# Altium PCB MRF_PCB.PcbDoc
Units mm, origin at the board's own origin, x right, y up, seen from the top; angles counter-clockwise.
Board outline 35 x 20 mm, 2 copper layers (Top Layer, Bottom Layer); 9 components, 16 nets, 39 pads, 10 vias.
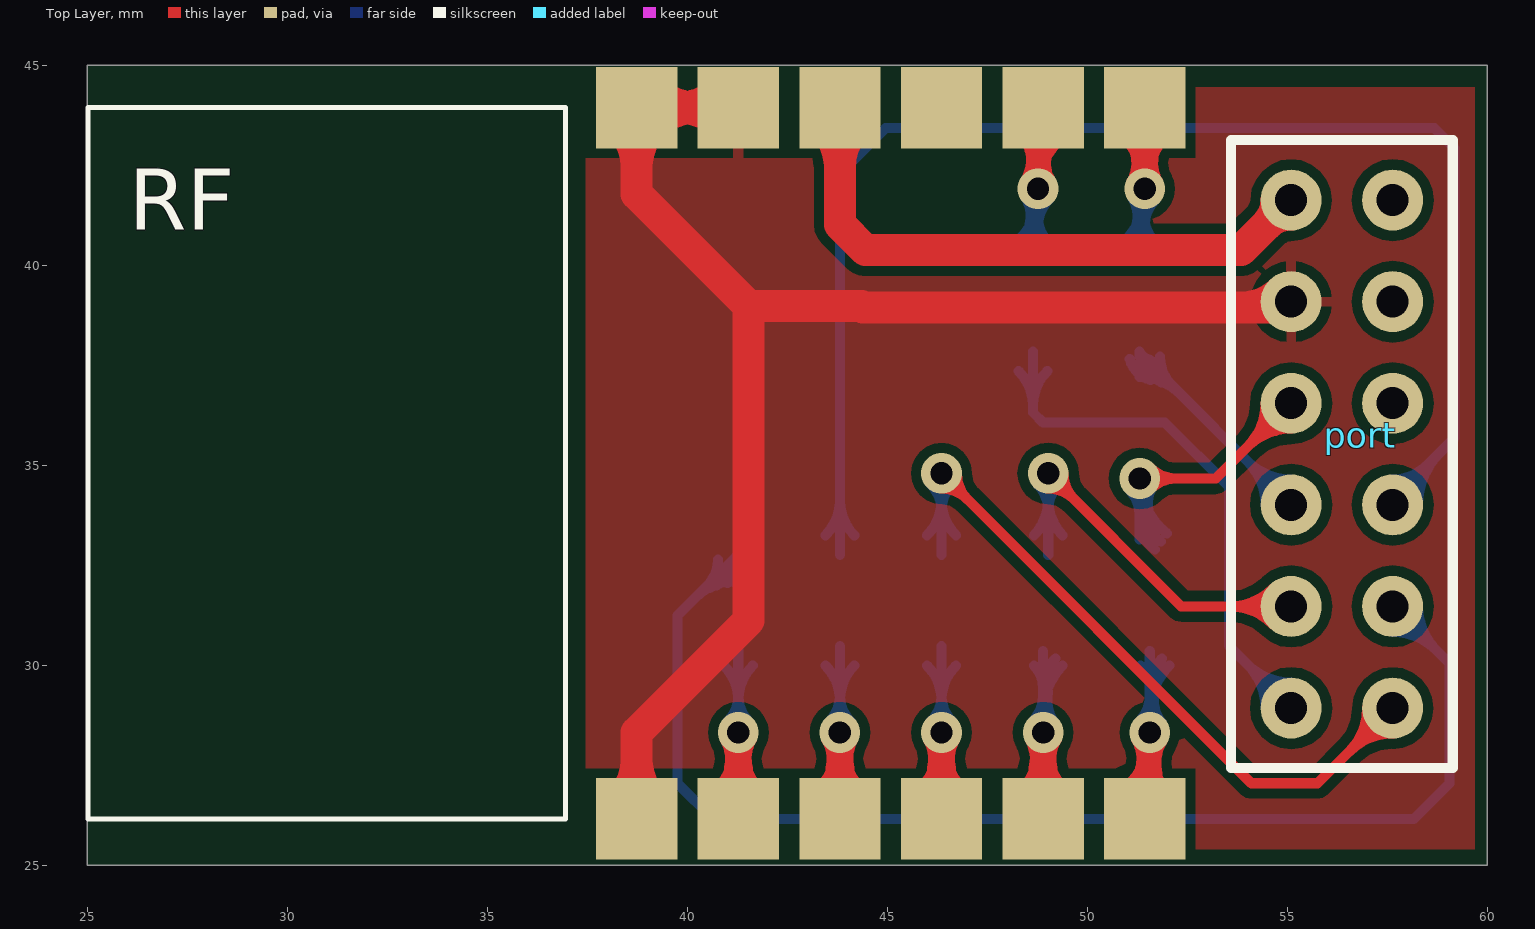
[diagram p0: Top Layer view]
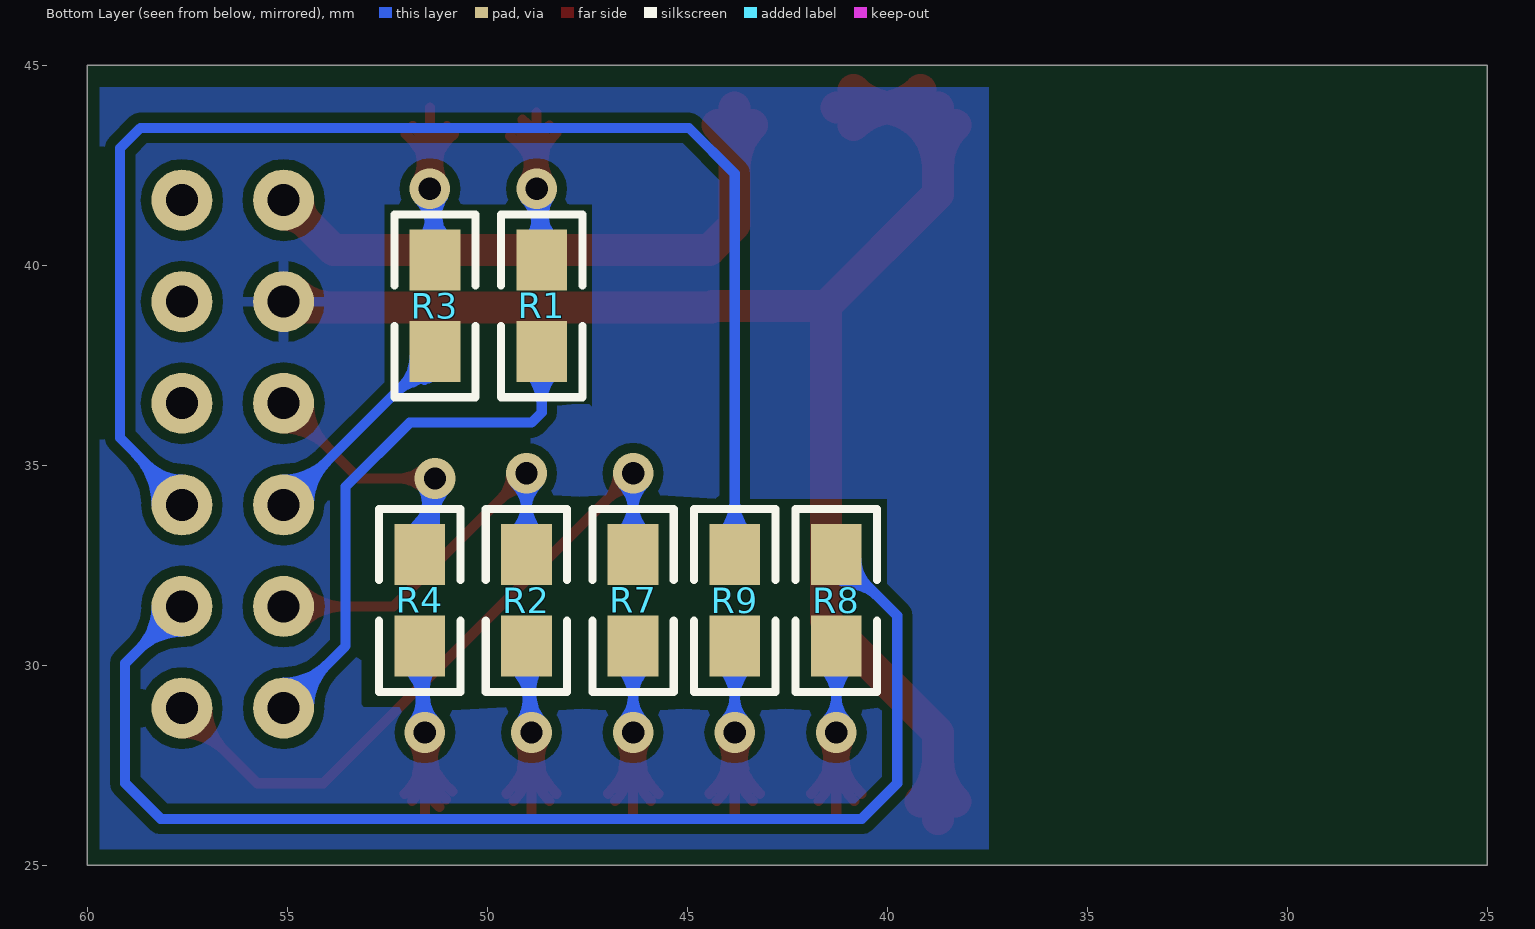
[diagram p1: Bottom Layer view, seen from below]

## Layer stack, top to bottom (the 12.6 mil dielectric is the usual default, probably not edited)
Top Solder: solder mask 0.0102, Solder Resist, Dk 3.5
Top Layer: signal copper 0.0356
Dielectric 1: dielectric 0.32, FR-4, Dk 4.8
Bottom Layer: signal copper 0.0356
Bottom Solder: solder mask 0.0102, Solder Resist, Dk 3.5

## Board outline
25,25 60,25 60,45 25,45

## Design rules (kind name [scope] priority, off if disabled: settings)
Clearance [All] p1: gap=0.254
PolygonConnect [All] p1: connectstyle=Relief reliefconductorwidth=0.254 reliefentries=4 polygonreliefangle="90 Angle" airgapwidth=0.254
RoutingVias [All] p1: holewidth=0.711 width=1.27 viastyle="Through Hole" minholewidth=0.711 minwidth=1.27 maxholewidth=0.711 maxwidth=1.27
SolderMaskExpansion [All] p1: expansion=0.102
Width [All] p1: maxlimit=0.8 minlimit=0.254 preferedwidth=0.254
29 further rules are at their usual default settings.

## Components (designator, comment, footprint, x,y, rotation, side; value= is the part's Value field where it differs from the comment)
port "Port" Port 53.594,27.432 r0 top
R1 "Res2" 0805 48.641,40.132 r270 bottom
R2 "Res2" 0805 49.022,30.48 r90 bottom
R3 "Res2" 0805 51.308,40.132 r270 bottom
R4 "Res2" 0805 51.689,30.48 r90 bottom
R7 "Res2" 0805 46.355,30.48 r90 bottom
R8 "Res2" 0805 41.275,30.48 r90 bottom
R9 "Res2" 0805 43.815,30.48 r90 bottom
RF "MRF Chip" MRF 25.019,26.162 r0 top

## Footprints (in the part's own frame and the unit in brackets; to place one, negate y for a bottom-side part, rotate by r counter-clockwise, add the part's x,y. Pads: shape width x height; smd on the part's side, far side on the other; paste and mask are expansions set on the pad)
0805 [mil]
  rect 60x50 smd: 1(0,0) 2(90,0)
  silkscreen extent -45,-40 135,40
MRF [mil]
  rect 80x80 smd: 1(540,0) 2(640,0) 3(740,0) 4(840,0) 5(940,0) 6(1040,0) 7(1040,700) 8(940,700) 9(840,700) 10(740,700) 11(640,700) 12(540,700)
  silkscreen extent 0,0 470,700
Port [mil] "Port 2x6"
  round 60 hole 31.5: 1(59.06,59.06) 2(59.06,159.06) 3(59.06,259.06) 4(59.06,359.06) 5(59.06,459.06) 6(59.06,559.06) 7(159.06,59.06) 8(159.06,159.06) 9(159.06,259.06) 10(159.06,359.06) 11(159.06,459.06) 12(159.06,559.06)
  round 19.68 on Top Overlay: 2(195,595)
  silkscreen extent 0,0 218,618

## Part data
R1 R2 R3 R4 R7 R8 R9: "Resistor"

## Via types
v1: diameter 1.016, hole 0.559, Top Layer to Bottom Layer, 10 vias

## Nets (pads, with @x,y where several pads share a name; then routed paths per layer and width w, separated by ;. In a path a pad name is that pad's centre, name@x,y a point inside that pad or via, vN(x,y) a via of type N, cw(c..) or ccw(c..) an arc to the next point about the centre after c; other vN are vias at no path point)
N1: R1.1 RF.8 | length 41.7
  Top Layer w0.254: v1(48.768,41.91) RF.8@48.768,43.815 ; v1@48.446,42.113 ccw(c47.631,42.626) 48.561,42.875 ; v1@48.446,42.113 ccw(c47.631,42.626) 48.561,42.875 ; v1@48.446,42.113 ccw(c47.631,42.626) 48.561,42.875 ; v1@48.578,42.24 ccw(c48.341,42.65) 48.798,42.527 ; v1@48.578,42.24 ccw(c48.341,42.65) 48.798,42.527 ; v1@48.578,42.24 ccw(c48.341,42.65) 48.798,42.527 ; v1@48.595,42.25 ccw(c48.247,42.937) 48.991,42.737 ; v1@48.595,42.25 ccw(c48.247,42.937) 48.991,42.737 ; v1@48.595,42.25 ccw(c48.247,42.937) 48.991,42.737 ; 48.609,42.695 ccw(c49.333,42.889) v1@48.959,42.24 ; 48.609,42.695 ccw(c49.333,42.889) v1@48.959,42.24 ; 48.609,42.695 ccw(c49.333,42.889) v1@48.959,42.24 ; 48.768,42.83 cw(c47.848,42.83) 48.499,42.179 ccw(c47.848,42.83) 48.768,42.83 ; 48.768,42.83 ccw(c49.688,42.83) 49.037,42.179 cw(c49.688,42.83) 48.768,42.83 ; 48.88,42.834 ccw(c49.561,42.652) v1@49.046,42.17 ; 48.88,42.834 ccw(c49.561,42.652) v1@49.046,42.17 ; 48.88,42.834 ccw(c49.561,42.652) v1@49.046,42.17 ; 48.991,42.737 ccw(c49.739,42.537) v1@49.088,42.117 ; 48.991,42.737 ccw(c49.739,42.537) v1@49.088,42.117 ; 48.991,42.737 ccw(c49.739,42.537) v1@49.088,42.117 ; RF.8@48.266,43.313 cw(c47.055,42.102) 48.768,42.102 ccw(c47.055,42.102) RF.8@48.266,43.313 ; RF.8@48.446,43.493 cw(c47.669,42.716) 48.768,42.716 ccw(c47.669,42.716) RF.8@48.446,43.493 ; v1@48.768,41.906 cw(c50.427,41.906) 49.429,43.232 ccw(c50.427,41.906) v1@48.768,41.906 ; v1@48.768,42.415 cw(c50.044,42.415) 49.277,43.435 ccw(c50.044,42.415) v1@48.768,42.415 ; 48.768,42.924 cw(c49.661,42.924) 49.124,43.638 ccw(c49.661,42.924) 48.768,42.924
  Bottom Layer w0.254: R1.1@48.768,40.259 v1(48.768,41.91) ; v1@48.449,41.701 cw(c47.735,41.234) 48.559,41.013 ; v1@48.449,41.701 cw(c47.735,41.234) 48.559,41.013 ; v1@48.449,41.701 cw(c47.735,41.234) 48.559,41.013 ; 48.579,41.085 cw(c49.366,40.874) v1@48.959,41.58 ; 48.579,41.085 cw(c49.366,40.874) v1@48.959,41.58 ; 48.579,41.085 cw(c49.366,40.874) v1@48.959,41.58 ; 48.768,40.99 cw(c49.688,40.99) 49.037,41.641 ccw(c49.688,40.99) 48.768,40.99 ; 48.768,40.99 ccw(c47.848,40.99) 48.499,41.641 cw(c47.848,40.99) 48.768,40.99 ; 48.768,41.179 cw(c47.721,41.179) 48.461,40.439 ccw(c47.721,41.179) 48.768,41.179 ; 48.768,41.179 ccw(c49.561,41.179) 49,40.618 cw(c49.561,41.179) 48.768,41.179 ; R1.1@48.282,40.618 ccw(c47.108,41.792) 48.768,41.792 cw(c47.108,41.792) R1.1@48.282,40.618
N2: R2.1 RF.5 | length 26.1
  Top Layer w0.254: RF.5@48.266,26.791 ccw(c46.749,28.308) 48.895,28.308 ccw(c51.041,28.308) RF.5@49.524,26.791 ; RF.5@48.446,26.611 ccw(c47.362,27.695) 48.895,27.695 ccw(c50.428,27.695) RF.5@49.344,26.611 ; v1@48.565,28.131 cw(c47.759,27.665) 48.658,27.424 ; v1@48.626,28.052 cw(c47.975,27.401) 48.895,27.401 cw(c49.815,27.401) v1@49.164,28.052 ; 48.662,27.439 cw(c49.54,27.204) v1@49.085,27.991 ; v1@48.705,27.991 cw(c48.25,27.204) 49.128,27.439 ; RF.5 v1(48.895,28.321) ; 49.132,27.424 cw(c50.031,27.665) v1@49.225,28.131
  Bottom Layer w0.254: v1(48.895,28.321) R2.1@48.895,30.353 ; 48.895,29.241 cw(c47.975,29.241) 48.626,28.59 ccw(c47.975,29.241) 48.895,29.241 ; 48.895,29.241 ccw(c49.815,29.241) 49.164,28.59 cw(c49.815,29.241) 48.895,29.241 ; 48.895,29.433 cw(c49.942,29.433) 49.202,30.173 ccw(c49.942,29.433) 48.895,29.433 ; 48.895,29.433 ccw(c48.102,29.433) 48.663,29.994 cw(c48.102,29.433) 48.895,29.433 ; v1@48.696,28.646 ccw(c48.421,29.092) 48.931,28.97 cw(c48.421,29.092) v1@48.696,28.646 ; v1@48.895,28.82 cw(c50.555,28.82) 49.381,29.994 ccw(c50.555,28.82) v1@48.895,28.82 ; 48.899,28.836 ccw(c49.399,28.717) 48.995,28.4 cw(c49.399,28.717) 48.899,28.836 ; 49.021,29.347 ccw(c49.925,29.131) 49.194,28.557 cw(c49.925,29.131) 49.021,29.347
N3: R3.1 RF.7 | length 25.8
  Top Layer w0.254: RF.7@50.832,43.289 cw(c49.557,41.91) v1(51.435,41.91) ; RF.7@51.004,43.476 cw(c50.094,42.491) 51.435,42.491 cw(c52.776,42.491) RF.7@51.866,43.476 ; v1@51.105,42.1 ccw(c50.308,42.56) 51.197,42.799 ccw(c52.085,43.036) v1@51.625,42.24 ; v1@51.166,42.179 ccw(c50.515,42.83) 51.435,42.83 ccw(c52.355,42.83) v1@51.704,42.179 ; v1@51.245,42.24 ccw(c50.785,43.036) 51.673,42.798 ccw(c52.562,42.56) v1@51.765,42.1 ; RF.7 v1(51.435,41.91) ; RF.7@52.038,43.289 ccw(c53.313,41.91) v1(51.435,41.91)
  Bottom Layer w0.254: R3.1@51.435,40.259 v1(51.435,41.91) ; v1@51.116,41.701 cw(c50.402,41.234) 51.226,41.013 ; v1@51.116,41.701 cw(c50.402,41.234) 51.226,41.013 ; v1@51.116,41.701 cw(c50.402,41.234) 51.226,41.013 ; 51.246,41.085 cw(c52.033,40.874) v1@51.626,41.58 ; 51.246,41.085 cw(c52.033,40.874) v1@51.626,41.58 ; 51.246,41.085 cw(c52.033,40.874) v1@51.626,41.58 ; 51.435,40.99 cw(c52.355,40.99) 51.704,41.641 ccw(c52.355,40.99) 51.435,40.99 ; 51.435,40.99 ccw(c50.515,40.99) 51.166,41.641 cw(c50.515,40.99) 51.435,40.99 ; 51.435,41.179 cw(c50.388,41.179) 51.128,40.439 ccw(c50.388,41.179) 51.435,41.179 ; 51.435,41.179 ccw(c52.228,41.179) 51.667,40.618 cw(c52.228,41.179) 51.435,41.179 ; R3.1@50.949,40.618 ccw(c49.775,41.792) 51.435,41.792 cw(c49.775,41.792) R3.1@50.949,40.618
N4: R4.1 RF.6 | length 26.2
  Top Layer w0.254: RF.6@50.868,26.847 ccw(c49.649,28.321) v1(51.562,28.321) RF.6@51.562,26.289 ; RF.6@51.03,26.651 ccw(c50.096,27.781) 51.562,27.781 ; RF.6@51.192,26.456 ccw(c50.542,27.241) 51.562,27.241 ; v1@51.232,28.13 cw(c50.435,27.671) 51.324,27.432 cw(c52.212,27.195) v1@51.753,27.991 ; v1@51.293,28.052 cw(c50.642,27.401) 51.562,27.401 cw(c52.482,27.401) v1@51.831,28.052 ; v1@51.372,27.991 cw(c51.053,27.439) 51.669,27.604 ; 51.562,27.388 ccw(c52.661,27.388) RF.6@51.884,26.611 ; v1@51.562,28.002 ccw(c53.275,28.002) RF.6@52.064,26.791 ; 51.754,27.284 cw(c52.763,27.554) v1@51.883,28.116
  Bottom Layer w0.254: v1(51.562,28.321) R4.1@51.562,30.353 ; 51.562,29.241 cw(c50.642,29.241) 51.293,28.59 ccw(c50.642,29.241) 51.562,29.241 ; 51.562,29.241 ccw(c52.482,29.241) 51.831,28.59 cw(c52.482,29.241) 51.562,29.241 ; 51.562,29.433 cw(c52.609,29.433) 51.869,30.173 ccw(c52.609,29.433) 51.562,29.433 ; 51.562,29.433 ccw(c50.769,29.433) 51.33,29.994 cw(c50.769,29.433) 51.562,29.433 ; v1@51.363,28.646 ccw(c51.088,29.092) 51.598,28.97 cw(c51.088,29.092) v1@51.363,28.646 ; v1@51.562,28.82 cw(c53.222,28.82) 52.048,29.994 ccw(c53.222,28.82) v1@51.562,28.82 ; 51.566,28.836 ccw(c52.066,28.717) 51.662,28.4 cw(c52.066,28.717) 51.566,28.836 ; 51.688,29.347 ccw(c52.592,29.131) 51.861,28.557 cw(c52.592,29.131) 51.688,29.347
N7: R7.1 RF.4 | length 21.2
  Top Layer w0.254: RF.4@45.726,26.791 ccw(c44.209,28.308) 46.355,28.308 ccw(c48.501,28.308) RF.4@46.984,26.791 ; RF.4@45.906,26.611 ccw(c44.822,27.695) 46.355,27.695 ccw(c47.888,27.695) RF.4@46.804,26.611 ; v1@46.025,28.131 cw(c45.219,27.665) 46.118,27.424 ; v1@46.086,28.052 cw(c45.435,27.401) 46.355,27.401 cw(c47.275,27.401) v1@46.624,28.052 ; 46.122,27.439 cw(c47,27.204) v1@46.545,27.991 ; v1@46.165,27.991 cw(c45.71,27.204) 46.588,27.439 ; RF.4 v1(46.355,28.321) ; 46.592,27.424 cw(c47.491,27.665) v1@46.685,28.131
  Bottom Layer w0.254: v1(46.355,28.321) R7.1 ; 46.355,29.127 cw(c47.581,29.127) 46.714,29.994 ccw(c47.581,29.127) 46.355,29.127 ; 46.355,29.127 ccw(c45.129,29.127) 45.996,29.994 cw(c45.129,29.127) 46.355,29.127 ; 46.355,29.241 cw(c45.435,29.241) 46.086,28.59 ccw(c45.435,29.241) 46.355,29.241 ; 46.355,29.241 ccw(c47.275,29.241) 46.624,28.59 cw(c47.275,29.241) 46.355,29.241
N8: R8.1 RF.2 | length 21.2
  Top Layer w0.254: RF.2@40.646,26.791 ccw(c39.129,28.308) 41.275,28.308 ccw(c43.421,28.308) RF.2@41.904,26.791 ; RF.2@40.826,26.611 ccw(c39.742,27.695) 41.275,27.695 ccw(c42.808,27.695) RF.2@41.724,26.611 ; v1@40.945,28.131 cw(c40.139,27.665) 41.038,27.424 ; v1@41.006,28.052 cw(c40.355,27.401) 41.275,27.401 cw(c42.195,27.401) v1@41.544,28.052 ; 41.042,27.439 cw(c41.92,27.204) v1@41.465,27.991 ; v1@41.085,27.991 cw(c40.63,27.204) 41.508,27.439 ; RF.2 v1(41.275,28.321) ; 41.512,27.424 cw(c42.411,27.665) v1@41.605,28.131
  Bottom Layer w0.254: v1(41.275,28.321) R8.1 ; 41.275,29.127 cw(c42.501,29.127) 41.634,29.994 ccw(c42.501,29.127) 41.275,29.127 ; 41.275,29.127 ccw(c40.049,29.127) 40.916,29.994 cw(c40.049,29.127) 41.275,29.127 ; 41.275,29.241 cw(c40.355,29.241) 41.006,28.59 ccw(c40.355,29.241) 41.275,29.241 ; 41.275,29.241 ccw(c42.195,29.241) 41.544,28.59 cw(c42.195,29.241) 41.275,29.241
N9: R9.1 RF.3 | length 21.2
  Top Layer w0.254: RF.3@43.186,26.791 ccw(c41.669,28.308) 43.815,28.308 ccw(c45.961,28.308) RF.3@44.444,26.791 ; RF.3@43.366,26.611 ccw(c42.282,27.695) 43.815,27.695 ccw(c45.348,27.695) RF.3@44.264,26.611 ; v1@43.485,28.131 cw(c42.679,27.665) 43.578,27.424 ; v1@43.546,28.052 cw(c42.895,27.401) 43.815,27.401 cw(c44.735,27.401) v1@44.084,28.052 ; 43.582,27.439 cw(c44.46,27.204) v1@44.005,27.991 ; v1@43.625,27.991 cw(c43.17,27.204) 44.048,27.439 ; RF.3 v1(43.815,28.321) ; 44.052,27.424 cw(c44.951,27.665) v1@44.145,28.131
  Bottom Layer w0.254: v1(43.815,28.321) R9.1 ; 43.815,29.127 cw(c45.041,29.127) 44.174,29.994 ccw(c45.041,29.127) 43.815,29.127 ; 43.815,29.127 ccw(c42.589,29.127) 43.456,29.994 cw(c42.589,29.127) 43.815,29.127 ; 43.815,29.241 cw(c42.895,29.241) 43.546,28.59 ccw(c42.895,29.241) 43.815,29.241 ; 43.815,29.241 ccw(c44.735,29.241) 44.084,28.59 cw(c44.735,29.241) 43.815,29.241
P1: port.1 R1.2 | length 21.1
  Bottom Layer w0.254: R1.2 48.641,36.322 48.895,36.068 51.943,36.068 53.546,34.465 53.546,30.48 port.1 ; port.1@54.459,28.932 ccw(c52.926,28.932) 54.01,30.016 ccw(c55.094,31.1) port.1@55.094,29.567 ; port.1@54.713,28.932 ccw(c53.793,28.932) 54.444,29.582 ccw(c55.094,30.233) port.1@55.094,29.313 ; 48.641,36.493 cw(c49.867,36.493) 49,37.36 ccw(c49.867,36.493) 48.641,36.493 ; 48.641,36.493 ccw(c47.415,36.493) 48.282,37.36 cw(c47.415,36.493) 48.641,36.493
P2: port.2@55.094,31.472 R2.2 | length 21.5
  Top Layer w0.254: v1@49.022,34.417 cw(c49.022,33.497) 49.672,34.148 cw(c50.323,34.798) v1@49.403,34.798 ; v1(49.022,34.798) 52.348,31.472 port.2@55.094,31.472 ; port.2@54.645,31.023 ccw(c53.561,29.939) 53.561,31.472 ccw(c53.561,33.005) port.2@54.645,31.921 ; port.2@54.825,31.203 ccw(c54.174,30.552) 54.174,31.472 ccw(c54.174,32.392) port.2@54.825,31.741
  Bottom Layer w0.254: R2.2 v1(49.022,34.798) ; 49.022,33.878 cw(c49.942,33.878) 49.291,34.529 ccw(c49.942,33.878) 49.022,33.878 ; 49.022,33.878 ccw(c48.102,33.878) 48.753,34.529 cw(c48.102,33.878) 49.022,33.878 ; 49.022,34.119 cw(c47.796,34.119) 48.663,33.252 ccw(c47.796,34.119) 49.022,34.119 ; 49.022,34.119 ccw(c50.248,34.119) 49.381,33.252 cw(c50.248,34.119) 49.022,34.119
P3: port.3 R3.2 | length 17.1
  Bottom Layer w0.254: R3.2@51.062,37.655 ccw(c51.76,37.837) R3.2@51.574,37.14 ; R3.2 51.308,37.798 port.3 ; 51.975,37.126 ccw(c51.191,36.916) 51.308,37.719 ccw(c52.246,37.963) 51.995,37.027 ; port.3@54.459,34.012 ccw(c52.926,34.012) 54.01,35.096 ccw(c55.094,36.18) port.3@55.094,34.647 ; port.3@54.713,34.012 ccw(c53.793,34.012) 54.444,34.662 ccw(c55.094,35.313) port.3@55.094,34.393 ; R3.2@51.308,37.211 cw(c51.308,35.794) 52.31,36.796 ccw(c51.308,35.794) R3.2@51.308,37.211 ; R3.2@51.308,37.465 cw(c51.308,36.661) 51.877,37.23 ccw(c51.308,36.661) R3.2@51.308,37.465 ; R3.2@51.816,37.719 ccw(c52.852,37.719) 52.119,36.987 cw(c52.852,37.719) R3.2@51.816,37.719
P4: port.4 R4.2 | length 26.1
  Top Layer w0.254: v1(51.308,34.671) 53.213,34.671 port.4 ; v1@51.577,34.402 cw(c52.228,33.751) 52.228,34.671 cw(c52.228,35.591) v1@51.577,34.94 ; port.4@54.459,36.552 cw(c52.926,36.552) 54.01,35.468 cw(c55.094,34.384) port.4@55.094,35.917 ; port.4@54.713,36.552 cw(c53.793,36.552) 54.444,35.902 cw(c55.094,35.251) port.4@55.094,36.171
  Bottom Layer w0.254: R4.2@51.308,33.147 v1(51.308,34.671) ; 51.49,33.543 ccw(c51.796,33.783) R4.2@51.75,33.397 ; v1@51.126,34.336 cw(c50.723,33.596) 51.538,33.814 ; v1@51.126,34.336 cw(c50.723,33.596) 51.538,33.814 ; v1@51.126,34.336 cw(c50.723,33.596) 51.538,33.814 ; 51.308,33.751 cw(c52.228,33.751) 51.577,34.402 ccw(c52.228,33.751) 51.308,33.751 ; 51.308,33.751 ccw(c50.388,33.751) 51.039,34.402 cw(c50.388,33.751) 51.308,33.751 ; v1(51.308,34.671) ccw(c53.022,34.671) 51.994,33.299 cw(c53.022,34.671) v1(51.308,34.671) ; 51.538,33.814 cw(c52.352,34.032) v1@51.633,34.472 ; 51.538,33.814 cw(c52.352,34.032) v1@51.633,34.472 ; 51.538,33.814 cw(c52.352,34.032) v1@51.633,34.472 ; 51.308,33.655 ccw(c52.26,33.655) 51.689,32.893 cw(c52.26,33.655) 51.308,33.655 ; 51.308,34.163 ccw(c52.641,34.163) 51.841,33.096 cw(c52.641,34.163) 51.308,34.163
P5: port.5 RF.1 RF.11 RF.12 | length 57.1
  Top Layer w0.8: RF.1 38.735,28.321 41.529,31.115 41.529,38.989 ; RF.11 RF.12 38.735,41.783 41.529,38.989 ; port.5 54.953,38.951 44.394,38.951 44.356,38.989 41.529,38.989 ; 38.735,27.649 cw(c37.248,27.649) 38.299,26.598 ccw(c37.248,27.649) 38.735,27.649 ; 38.735,27.649 ccw(c40.222,27.649) 39.171,26.598 cw(c40.222,27.649) 38.735,27.649 ; 38.735,42.455 cw(c40.222,42.455) RF.12@39.171,43.506 ; 38.735,42.455 ccw(c37.248,42.455) 38.299,43.506 cw(c37.248,42.455) 38.735,42.455 ; 38.735,42.455 cw(c40.222,42.455) RF.12@39.171,43.506 ; RF.12@39.171,43.506 cw(c40.222,42.455) 40.222,43.942 ; RF.12@39.171,43.506 cw(c40.222,42.455) 40.222,43.942 ; 39.788,43.942 cw(c39.788,42.455) 40.839,43.506 ccw(c39.788,42.455) 39.788,43.942 ; 39.788,43.942 ccw(c39.788,45.429) 40.839,44.378 cw(c39.788,45.429) 39.788,43.942 ; 40.222,43.942 cw(c40.222,45.429) 39.171,44.378 ccw(c40.222,45.429) 40.222,43.942 ; 53.88,38.951 ccw(c53.88,40.306) 54.838,39.348 cw(c53.88,40.306) 53.88,38.951
P6: port.6 RF.10 | length 18.7
  Top Layer w0.8: RF.10@43.379,43.506 cw(c42.328,42.455) 43.815,42.455 cw(c45.302,42.455) RF.10@44.251,43.506 ; RF.10 43.815,41.021 44.45,40.386 53.848,40.386 port.6 ; port.6@54.732,41.632 cw(c53.858,41.632) 54.476,41.014 cw(c55.094,40.396) port.6@55.094,41.27
P7: port.7 R7.2 | length 29.3
  Top Layer w0.254: v1@46.355,34.417 cw(c46.355,33.497) 47.005,34.148 cw(c47.656,34.798) v1@46.736,34.798 ; v1(46.355,34.798) 54.102,27.051 55.753,27.051 port.7 ; port.7@56.999,28.932 cw(c55.466,28.932) 56.55,27.848 cw(c57.634,26.764) port.7@57.634,28.297 ; port.7@57.253,28.932 cw(c56.333,28.932) 56.984,28.282 cw(c57.634,27.631) port.7@57.634,28.551
  Bottom Layer w0.254: R7.2 v1(46.355,34.798) ; 46.355,33.878 cw(c47.275,33.878) 46.624,34.529 ccw(c47.275,33.878) 46.355,33.878 ; 46.355,33.878 ccw(c45.435,33.878) 46.086,34.529 cw(c45.435,33.878) 46.355,33.878 ; 46.355,34.119 cw(c45.129,34.119) 45.996,33.252 ccw(c45.129,34.119) 46.355,34.119 ; 46.355,34.119 ccw(c47.581,34.119) 46.714,33.252 cw(c47.581,34.119) 46.355,34.119
P8: port.8 R8.2 | length 42.4
  Bottom Layer w0.254: 40.56,31.939 ccw(c40.296,32.925) R8.2@41.275,32.639 ; R8.2@40.996,32.056 ccw(c40.803,32.777) R8.2@41.519,32.568 ; R8.2 39.751,31.242 39.751,27.051 40.64,26.162 58.166,26.162 59.055,27.051 59.055,30.051 port.8 ; port.8@57.634,30.837 cw(c57.634,29.304) 58.718,30.388 cw(c59.802,31.472) port.8@58.269,31.472 ; port.8@57.634,31.091 cw(c57.634,30.171) 58.284,30.822 cw(c58.935,31.472) port.8@58.015,31.472 ; 40.191,31.682 cw(c41.275,30.598) 41.275,32.131 ccw(c41.275,30.598) 40.191,31.682 ; 40.498,31.989 ccw(c39.847,32.639) 40.767,32.639 cw(c39.847,32.639) 40.498,31.989 ; 40.625,32.116 cw(c41.275,31.465) 41.275,32.385 ccw(c41.275,31.465) 40.625,32.116
P9: port.9 R9.2 | length 42.4
  Bottom Layer w0.254: R9.2 43.815,42.291 44.958,43.434 58.674,43.434 59.182,42.926 59.182,35.687 57.634,34.139 port.9 ; port.9@57.634,34.647 ccw(c57.634,35.873) 58.501,35.006 ; port.9@58.015,34.012 cw(c59.241,34.012) 58.374,34.879 ; port.9@58.269,34.012 cw(c60.109,34.012) 58.808,35.313 ; 43.815,34.119 cw(c42.589,34.119) 43.456,33.252 ccw(c42.589,34.119) 43.815,34.119 ; 43.815,34.119 ccw(c45.041,34.119) 44.174,33.252 cw(c45.041,34.119) 43.815,34.119
pads on no net: port.2@58.547,42.545 port.10 port.11 port.12 RF.9

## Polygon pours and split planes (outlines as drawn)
P5 on Bottom Layer "Bottom Layer-No Net" (solid, remove dead copper, pour order 4): 37.465,44.45 59.69,44.45 59.69,25.4 37.465,25.4
P5 on Top Layer "Bottom Layer-No Net" (solid, remove dead copper, pour order 6): 37.465,44.45 59.69,44.45 59.69,25.4 37.465,25.4

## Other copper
Bottom Layer:
  pour cut-out: 40.005,34.163 53.122,34.163 53.158,34.128 53.158,29.028 53.086,28.956 40.005,28.956
  pour cut-out: 47.371,41.529 52.578,41.529 52.578,36.528 47.45,36.528 47.371,36.449

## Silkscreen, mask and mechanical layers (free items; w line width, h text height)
Mechanical 1:
  the board outline again, w0.127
